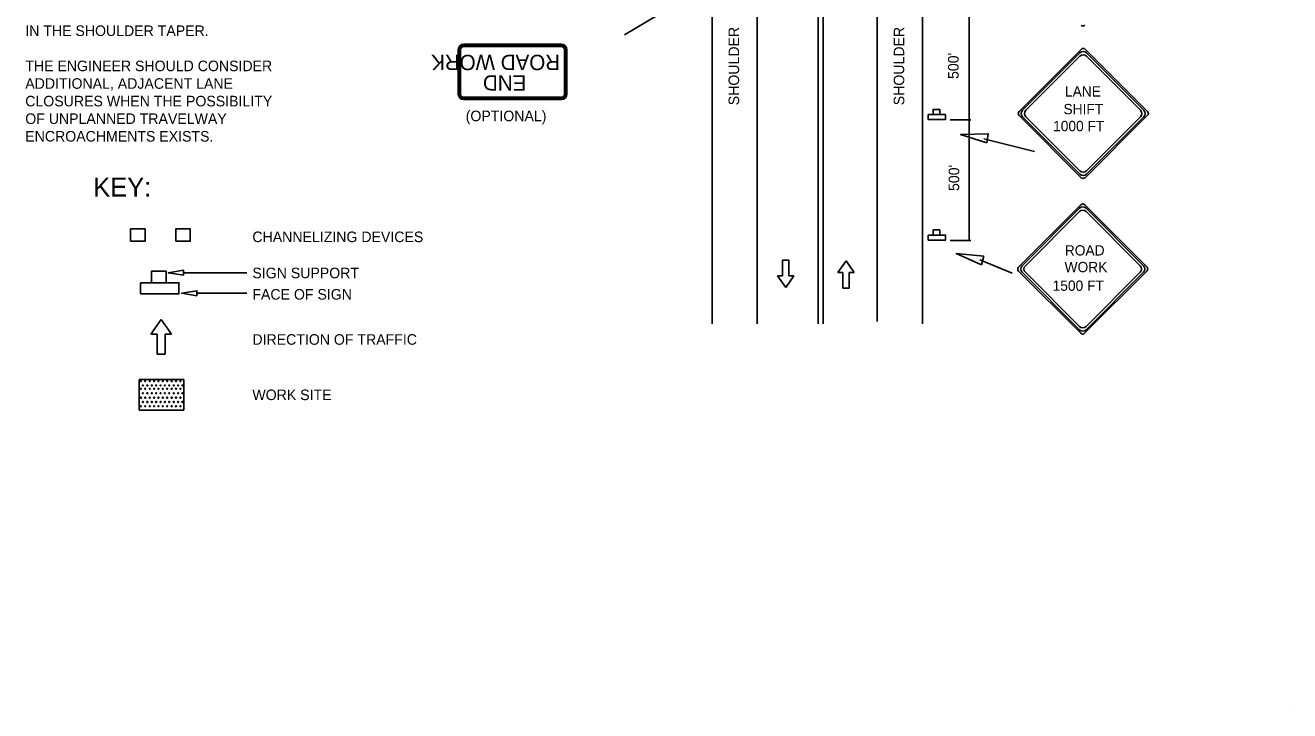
# Model space of a CAD drawing. Extents: x 1531.38 to 1538.58, y 1529.59 to 1539.28.
# Drawn here: x 1531.39 to 1538.58, y 1529.59 to 1533.49 of the extents above; entities that cross this region are included whole.
import ezdxf

# ---------------------------------------------------------------- set-up
doc = ezdxf.new("R2010")
doc.units = 0
for name, color, linetype in [('DETL-DIMS', 7, 'Continuous'), ('DETL-LINE', 7, 'Continuous'), ('DETL-NOTE', 7, 'Continuous'), ('DETL-TITL', 7, 'Continuous'), ('TTLB-TEXT', 7, 'Continuous'), ('USER-BORD', 7, 'Continuous')]:
    doc.layers.add(name, color=color, linetype=linetype)

# ---------------------------------------------------------------- blocks, each defined once
blk = doc.blocks.new('SIGN13')
at = {"layer": 'USER-BORD'}
for points in [[(-0.0134, 0.0182), (0.011, 0.0189), (0.011, 0.0371), (-0.0134, 0.0371)], [(-0.0314, 0.0182), (-0.0314, 0), (0.032, 0), (0.032, 0.0182)]]:
    blk.add_lwpolyline(points, close=True, dxfattribs=at)
blk = doc.blocks.new('DIR2')
at = {"layer": 'USER-BORD'}
for p, q in [((0, 0.0012), (-0.0342, -0.0477)), ((0, 0.0012), (0.0342, -0.0477)), ((-0.0342, -0.0477), (-0.0132, -0.0477)), ((-0.0132, -0.1133), (-0.0132, -0.0477)), ((0.0342, -0.0477), (0.0132, -0.0477)), ((0.0132, -0.1133), (0.0132, -0.0477)), ((-0.0011, -0.1133), (-0.0132, -0.1133)), ((-0.0011, -0.1133), (0.0011, -0.1133)), ((0.0011, -0.1133), (0.0132, -0.1133))]:
    blk.add_line(p, q, dxfattribs=at)
blk = doc.blocks.new('TD')
at = {"layer": 'USER-BORD'}
for p, q in [((0, 0), (-0.0539, -0.077)), ((0, 0), (0.0539, -0.077)), ((-0.0539, -0.077), (-0.0208, -0.077)), ((-0.0208, -0.1803), (-0.0208, -0.077)), ((0.0208, -0.1803), (0.0208, -0.077)), ((0.0539, -0.077), (0.0208, -0.077)), ((-0.0017, -0.1803), (-0.0208, -0.1803)), ((-0.0017, -0.1803), (0.0017, -0.1803)), ((0.0017, -0.1803), (0.0208, -0.1803))]:
    blk.add_line(p, q, dxfattribs=at)

msp = doc.modelspace()

# ---------------------------------------------------------------- linework, layer by layer
at = {"layer": 'DETL-DIMS'}
for p, q in [((1536.7613, 1535.4484), (1536.7613, 1533.1366)), ((1536.7613, 1534.4003), (1536.7613, 1532.2659)), ((1534.9925, 1533.5485), (1534.8025, 1533.4337)), ((1536.6537, 1532.9513), (1536.7703, 1532.9513)), ((1536.8443, 1532.8441), (1537.1327, 1532.7711)), ((1536.6537, 1532.2659), (1536.7703, 1532.2659)), ((1536.823, 1532.1553), (1537.0061, 1532.0801)), ((1532.2934, 1532.0824), (1532.6543, 1532.0824)), ((1532.3705, 1531.9657), (1532.6543, 1531.9657))]:
    msp.add_line(p, q, dxfattribs=at)
for points in [[(1536.8627, 1532.8207), (1536.8701, 1532.8719), (1536.7129, 1532.8682)], [(1536.8313, 1532.1263), (1536.8447, 1532.1763), (1536.6882, 1532.1911)], [(1532.2934, 1532.068), (1532.2934, 1532.0967), (1532.2073, 1532.0824)], [(1532.3705, 1531.9513), (1532.3705, 1531.98), (1532.2844, 1531.9657)]]:
    msp.add_lwpolyline(points, close=True, dxfattribs=at)
at = {"layer": 'DETL-LINE'}
for p, q in [((1535.3002, 1538.9346), (1535.3002, 1531.7918)), ((1535.5552, 1538.9346), (1535.5552, 1531.7918)), ((1535.9039, 1538.9346), (1535.9039, 1531.7918)), ((1535.9309, 1538.9346), (1535.9309, 1531.7918)), ((1536.4962, 1538.9346), (1536.4962, 1531.7918)), ((1536.2393, 1535.6775), (1536.2393, 1531.8053)), ((1533.8562, 1533.3497), (1533.8562, 1533.0974)), ((1533.8626, 1533.0974), (1533.8626, 1533.3497)), ((1533.8699, 1533.0974), (1533.8699, 1533.3497)), ((1534.4426, 1533.3813), (1533.8879, 1533.3813)), ((1533.8879, 1533.3749), (1534.4426, 1533.3749)), ((1533.8879, 1533.3677), (1534.4426, 1533.3677)), ((1534.4609, 1533.3497), (1534.4609, 1533.0974)), ((1534.4676, 1533.3497), (1534.4676, 1533.0974)), ((1534.474, 1533.0974), (1534.474, 1533.3497)), ((1537.4002, 1533.3529), (1537.0455, 1532.9982)), ((1537.7761, 1532.9989), (1537.4221, 1533.3529)), ((1537.0654, 1533.0065), (1537.3915, 1533.3327)), ((1537.3915, 1533.3139), (1537.0843, 1533.0065)), ((1537.7366, 1533.0065), (1537.4292, 1533.3139)), ((1537.4293, 1533.3327), (1537.7554, 1533.0065)), ((1533.8698, 1533.0976), (1533.8699, 1533.0974)), ((1534.4426, 1533.0792), (1533.8879, 1533.0792)), ((1534.4426, 1533.0725), (1533.8879, 1533.0725)), ((1533.8879, 1533.0661), (1534.4426, 1533.0661)), ((1537.7366, 1533.0065), (1537.7366, 1533.0065)), ((1537.0455, 1532.9762), (1537.3994, 1532.6223)), ((1537.3915, 1532.6427), (1537.0654, 1532.9688)), ((1537.0843, 1532.9689), (1537.3915, 1532.6615)), ((1537.4214, 1532.6223), (1537.7761, 1532.977)), ((1537.7554, 1532.9688), (1537.4293, 1532.6427)), ((1537.4293, 1532.6615), (1537.7366, 1532.9688)), ((1537.3971, 1532.4685), (1537.0423, 1532.1138)), ((1537.0623, 1532.1221), (1537.3884, 1532.4483)), ((1537.3884, 1532.4295), (1537.0811, 1532.1221)), ((1537.7729, 1532.1146), (1537.419, 1532.4685)), ((1537.4261, 1532.4483), (1537.7523, 1532.1221)), ((1537.7335, 1532.1221), (1537.4261, 1532.4295)), ((1537.0423, 1532.0919), (1537.3963, 1531.7379)), ((1537.3884, 1531.7583), (1537.0623, 1532.0845)), ((1537.0811, 1532.0845), (1537.3884, 1531.7771)), ((1537.4183, 1531.7379), (1537.7729, 1532.0926)), ((1537.7523, 1532.0845), (1537.4261, 1531.7583)), ((1537.4261, 1531.7771), (1537.7335, 1532.0845)), ((1537.7335, 1532.1221), (1537.7335, 1532.1221)), ((1532.0421, 1531.3011), (1532.0421, 1531.4751)), ((1532.0421, 1531.3011), (1532.0421, 1531.4751)), ((1532.2961, 1531.475), (1532.0421, 1531.475)), ((1532.2961, 1531.475), (1532.0421, 1531.475)), ((1532.2961, 1531.475), (1532.0421, 1531.475)), ((1532.2961, 1531.475), (1532.0421, 1531.475)), ((1532.0507, 1531.4661), (1532.0507, 1531.4661)), ((1532.0507, 1531.4223), (1532.0507, 1531.4223)), ((1532.0515, 1531.4661), (1532.0515, 1531.4661)), ((1532.0515, 1531.4223), (1532.0515, 1531.4223)), ((1532.0635, 1531.4413), (1532.0635, 1531.4413)), ((1532.0635, 1531.4413), (1532.0635, 1531.4413)), ((1532.0763, 1531.4661), (1532.0763, 1531.4661)), ((1532.0763, 1531.4661), (1532.0763, 1531.4661)), ((1532.0763, 1531.4223), (1532.0763, 1531.4223)), ((1532.0763, 1531.4223), (1532.0763, 1531.4223)), ((1532.0883, 1531.4413), (1532.0883, 1531.4413)), ((1532.0883, 1531.4413), (1532.0883, 1531.4413)), ((1532.1011, 1531.4661), (1532.1011, 1531.4661)), ((1532.1011, 1531.4223), (1532.1011, 1531.4223)), ((1532.1019, 1531.4661), (1532.1019, 1531.4661)), ((1532.1019, 1531.4223), (1532.1019, 1531.4223)), ((1532.1139, 1531.4413), (1532.1139, 1531.4413)), ((1532.1139, 1531.4413), (1532.1139, 1531.4413)), ((1532.1259, 1531.4661), (1532.1259, 1531.4661)), ((1532.1259, 1531.4223), (1532.1259, 1531.4223)), ((1532.1267, 1531.4661), (1532.1267, 1531.4661)), ((1532.1267, 1531.4223), (1532.1267, 1531.4223)), ((1532.1387, 1531.4413), (1532.1387, 1531.4413)), ((1532.1387, 1531.4413), (1532.1387, 1531.4413)), ((1532.1507, 1531.4661), (1532.1507, 1531.4661)), ((1532.1507, 1531.4223), (1532.1507, 1531.4223)), ((1532.1515, 1531.4661), (1532.1515, 1531.4661)), ((1532.1515, 1531.4223), (1532.1515, 1531.4223)), ((1532.1635, 1531.4413), (1532.1635, 1531.4413)), ((1532.1635, 1531.4413), (1532.1635, 1531.4413)), ((1532.1763, 1531.4661), (1532.1763, 1531.4661)), ((1532.1763, 1531.4661), (1532.1763, 1531.4661)), ((1532.1763, 1531.4223), (1532.1763, 1531.4223)), ((1532.1763, 1531.4223), (1532.1763, 1531.4223)), ((1532.1883, 1531.4413), (1532.1883, 1531.4413)), ((1532.1883, 1531.4413), (1532.1883, 1531.4413)), ((1532.2011, 1531.4661), (1532.2011, 1531.4661)), ((1532.2011, 1531.4661), (1532.2011, 1531.4661)), ((1532.2011, 1531.4223), (1532.2011, 1531.4223)), ((1532.2011, 1531.4223), (1532.2011, 1531.4223)), ((1532.2131, 1531.4413), (1532.2131, 1531.4413)), ((1532.2131, 1531.4413), (1532.2131, 1531.4413)), ((1532.2259, 1531.4661), (1532.2259, 1531.4661)), ((1532.2259, 1531.4223), (1532.2259, 1531.4223)), ((1532.2267, 1531.4661), (1532.2267, 1531.4661)), ((1532.2267, 1531.4223), (1532.2267, 1531.4223)), ((1532.2387, 1531.4413), (1532.2387, 1531.4413)), ((1532.2387, 1531.4413), (1532.2387, 1531.4413)), ((1532.2507, 1531.4661), (1532.2507, 1531.4661)), ((1532.2507, 1531.4223), (1532.2507, 1531.4223)), ((1532.2515, 1531.4661), (1532.2515, 1531.4661)), ((1532.2515, 1531.4223), (1532.2515, 1531.4223)), ((1532.2635, 1531.4413), (1532.2635, 1531.4413)), ((1532.2635, 1531.4413), (1532.2635, 1531.4413)), ((1532.2763, 1531.4661), (1532.2763, 1531.4661)), ((1532.2763, 1531.4661), (1532.2763, 1531.4661)), ((1532.2763, 1531.4223), (1532.2763, 1531.4223)), ((1532.2763, 1531.4223), (1532.2763, 1531.4223)), ((1532.2883, 1531.4413), (1532.2883, 1531.4413)), ((1532.2883, 1531.4413), (1532.2883, 1531.4413)), ((1532.2961, 1531.301), (1532.2961, 1531.475)), ((1532.2961, 1531.301), (1532.2961, 1531.475)), ((1532.2961, 1531.301), (1532.2961, 1531.475)), ((1532.2961, 1531.301), (1532.2961, 1531.475)), ((1532.0507, 1531.3719), (1532.0507, 1531.3719)), ((1532.0515, 1531.3719), (1532.0515, 1531.3719)), ((1532.0635, 1531.3967), (1532.0635, 1531.3967)), ((1532.0635, 1531.3471), (1532.0635, 1531.3471)), ((1532.0635, 1531.3471), (1532.0635, 1531.3471)), ((1532.0763, 1531.3719), (1532.0763, 1531.3719)), ((1532.0763, 1531.3719), (1532.0763, 1531.3719)), ((1532.0883, 1531.3967), (1532.0883, 1531.3967)), ((1532.0883, 1531.3471), (1532.0883, 1531.3471)), ((1532.0883, 1531.3471), (1532.0883, 1531.3471)), ((1532.1011, 1531.3719), (1532.1011, 1531.3719)), ((1532.1019, 1531.3719), (1532.1019, 1531.3719)), ((1532.1139, 1531.3967), (1532.1139, 1531.3967)), ((1532.1139, 1531.3471), (1532.1139, 1531.3471)), ((1532.1139, 1531.3471), (1532.1139, 1531.3471)), ((1532.1259, 1531.3719), (1532.1259, 1531.3719)), ((1532.1267, 1531.3719), (1532.1267, 1531.3719)), ((1532.1387, 1531.3967), (1532.1387, 1531.3967)), ((1532.1387, 1531.3471), (1532.1387, 1531.3471)), ((1532.1387, 1531.3471), (1532.1387, 1531.3471)), ((1532.1507, 1531.3719), (1532.1507, 1531.3719)), ((1532.1515, 1531.3719), (1532.1515, 1531.3719)), ((1532.1635, 1531.3967), (1532.1635, 1531.3967)), ((1532.1635, 1531.3471), (1532.1635, 1531.3471)), ((1532.1635, 1531.3471), (1532.1635, 1531.3471)), ((1532.1763, 1531.3719), (1532.1763, 1531.3719)), ((1532.1763, 1531.3719), (1532.1763, 1531.3719)), ((1532.1883, 1531.3967), (1532.1883, 1531.3967)), ((1532.1883, 1531.3471), (1532.1883, 1531.3471)), ((1532.1883, 1531.3471), (1532.1883, 1531.3471)), ((1532.2011, 1531.3719), (1532.2011, 1531.3719)), ((1532.2011, 1531.3719), (1532.2011, 1531.3719)), ((1532.2131, 1531.3967), (1532.2131, 1531.3967)), ((1532.2131, 1531.3471), (1532.2131, 1531.3471)), ((1532.2131, 1531.3471), (1532.2131, 1531.3471)), ((1532.2259, 1531.3719), (1532.2259, 1531.3719)), ((1532.2267, 1531.3719), (1532.2267, 1531.3719)), ((1532.2387, 1531.3967), (1532.2387, 1531.3967)), ((1532.2387, 1531.3471), (1532.2387, 1531.3471)), ((1532.2387, 1531.3471), (1532.2387, 1531.3471)), ((1532.2507, 1531.3719), (1532.2507, 1531.3719)), ((1532.2515, 1531.3719), (1532.2515, 1531.3719)), ((1532.2635, 1531.3967), (1532.2635, 1531.3967)), ((1532.2635, 1531.3471), (1532.2635, 1531.3471)), ((1532.2635, 1531.3471), (1532.2635, 1531.3471)), ((1532.2763, 1531.3719), (1532.2763, 1531.3719)), ((1532.2763, 1531.3719), (1532.2763, 1531.3719)), ((1532.2883, 1531.3967), (1532.2883, 1531.3967)), ((1532.2883, 1531.3471), (1532.2883, 1531.3471)), ((1532.2883, 1531.3471), (1532.2883, 1531.3471)), ((1532.0421, 1531.3011), (1532.2961, 1531.3011)), ((1532.0507, 1531.3227), (1532.0507, 1531.3227)), ((1532.0515, 1531.3227), (1532.0515, 1531.3227)), ((1532.0763, 1531.3227), (1532.0763, 1531.3227)), ((1532.0763, 1531.3227), (1532.0763, 1531.3227)), ((1532.1011, 1531.3227), (1532.1011, 1531.3227)), ((1532.1019, 1531.3227), (1532.1019, 1531.3227)), ((1532.1259, 1531.3227), (1532.1259, 1531.3227)), ((1532.1267, 1531.3227), (1532.1267, 1531.3227)), ((1532.1507, 1531.3227), (1532.1507, 1531.3227)), ((1532.1515, 1531.3227), (1532.1515, 1531.3227)), ((1532.1763, 1531.3227), (1532.1763, 1531.3227)), ((1532.1763, 1531.3227), (1532.1763, 1531.3227)), ((1532.2011, 1531.3227), (1532.2011, 1531.3227)), ((1532.2011, 1531.3227), (1532.2011, 1531.3227)), ((1532.2259, 1531.3227), (1532.2259, 1531.3227)), ((1532.2267, 1531.3227), (1532.2267, 1531.3227)), ((1532.2507, 1531.3227), (1532.2507, 1531.3227)), ((1532.2515, 1531.3227), (1532.2515, 1531.3227)), ((1532.2763, 1531.3227), (1532.2763, 1531.3227)), ((1532.2763, 1531.3227), (1532.2763, 1531.3227))]:
    msp.add_line(p, q, dxfattribs=at)
for points in [[(1531.9928, 1532.2613), (1531.9928, 1532.3309), (1532.0754, 1532.3309), (1532.0754, 1532.2613)], [(1532.2498, 1532.2613), (1532.2498, 1532.3309), (1532.3324, 1532.3309), (1532.3324, 1532.2613)]]:
    msp.add_lwpolyline(points, close=True, dxfattribs=at)
for centre in [(1532.0514, 1531.4661), (1532.0514, 1531.4224), (1532.0634, 1531.4413), (1532.0762, 1531.4661), (1532.0762, 1531.4224), (1532.0882, 1531.4413), (1532.1018, 1531.4661), (1532.1018, 1531.4224), (1532.1138, 1531.4413), (1532.1266, 1531.4661), (1532.1266, 1531.4224), (1532.1386, 1531.4413), (1532.1514, 1531.4661), (1532.1514, 1531.4224), (1532.1634, 1531.4413), (1532.1762, 1531.4661), (1532.1762, 1531.4224), (1532.1882, 1531.4413), (1532.201, 1531.4661), (1532.201, 1531.4224), (1532.213, 1531.4413), (1532.2266, 1531.4661), (1532.2266, 1531.4224), (1532.2386, 1531.4413), (1532.2514, 1531.4661), (1532.2514, 1531.4224), (1532.2634, 1531.4413), (1532.2762, 1531.4661), (1532.2762, 1531.4224), (1532.2882, 1531.4413), (1532.0514, 1531.372), (1532.0634, 1531.3968), (1532.0634, 1531.3472), (1532.0762, 1531.372), (1532.0882, 1531.3968), (1532.0882, 1531.3472), (1532.1018, 1531.372), (1532.1138, 1531.3968), (1532.1138, 1531.3472), (1532.1266, 1531.372), (1532.1386, 1531.3968), (1532.1386, 1531.3472), (1532.1514, 1531.372), (1532.1634, 1531.3968), (1532.1634, 1531.3472), (1532.1762, 1531.372), (1532.1882, 1531.3968), (1532.1882, 1531.3472), (1532.201, 1531.372), (1532.213, 1531.3968), (1532.213, 1531.3472), (1532.2266, 1531.372), (1532.2386, 1531.3968), (1532.2386, 1531.3472), (1532.2514, 1531.372), (1532.2634, 1531.3968), (1532.2634, 1531.3472), (1532.2762, 1531.372), (1532.2882, 1531.3968), (1532.2882, 1531.3472), (1532.0514, 1531.3228), (1532.0762, 1531.3228), (1532.1018, 1531.3228), (1532.1266, 1531.3228), (1532.1514, 1531.3228), (1532.1762, 1531.3228), (1532.201, 1531.3228), (1532.2266, 1531.3228), (1532.2514, 1531.3228), (1532.2762, 1531.3228)]:
    msp.add_circle(centre, 0.00291, dxfattribs=at)
for centre, radius, start, end in [((1537.4086, 1533.4996), 0.0155, 225, 315), ((1533.8879, 1533.3497), 0.0316, 90, 180), ((1533.8879, 1533.3497), 0.0252, 90, 180), ((1533.8879, 1533.3497), 0.0181, 90, 180), ((1534.4425, 1533.3497), 0.0316, 0, 90), ((1534.4425, 1533.3497), 0.0252, 0, 90), ((1534.4425, 1533.3497), 0.0181, 0, 90), ((1537.4112, 1533.3419), 0.0155, 45, 135), ((1537.4104, 1533.3138), 0.0266, 45, 135), ((1537.4104, 1533.295), 0.0266, 45, 135), ((1533.8879, 1533.0976), 0.0316, 180, 270), ((1533.8879, 1533.0976), 0.0252, 180, 270), ((1533.8879, 1533.0976), 0.0181, 180, 270), ((1534.4425, 1533.0976), 0.0316, 270, 0), ((1534.4425, 1533.0976), 0.0252, 270, 0), ((1534.4425, 1533.0976), 0.0181, 270, 0), ((1537.0565, 1532.9872), 0.0155, 135, 225), ((1537.0842, 1532.9876), 0.0266, 135, 225), ((1537.103, 1532.9877), 0.0266, 135, 225), ((1537.7178, 1532.9876), 0.0266, 315, 45), ((1537.7366, 1532.9876), 0.0266, 315, 45), ((1537.7651, 1532.988), 0.0155, 315, 45), ((1537.4104, 1532.6803), 0.0266, 225, 315), ((1537.4104, 1532.6614), 0.0266, 225, 315), ((1537.4104, 1532.6332), 0.0155, 225, 315), ((1537.4073, 1532.4107), 0.0266, 45, 135), ((1537.4073, 1532.4295), 0.0266, 45, 135), ((1537.4081, 1532.4575), 0.0155, 45, 135), ((1537.0533, 1532.1028), 0.0155, 135, 225), ((1537.0811, 1532.1033), 0.0266, 135, 225), ((1537.0999, 1532.1033), 0.0266, 135, 225), ((1537.7146, 1532.1033), 0.0266, 315, 45), ((1537.7335, 1532.1033), 0.0266, 315, 45), ((1537.762, 1532.1036), 0.0155, 315, 45), ((1537.4073, 1531.7959), 0.0266, 225, 315), ((1537.4073, 1531.7771), 0.0266, 225, 315), ((1537.4073, 1531.7489), 0.0155, 225, 315)]:
    msp.add_arc(centre, radius, start, end, dxfattribs=at)
at = {"layer": 'TTLB-TEXT'}
msp.add_line((1538.5844, 1529.5924), (1538.5844, 1529.5924), dxfattribs=at)

# ---------------------------------------------------------------- block references
at = {"layer": 'DETL-LINE'}
for name, p, xscale, yscale in [('SIGN13', (1536.5771, 1532.9533), 1.550372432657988, 1.550372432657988), ('SIGN13', (1536.5777, 1532.2679), 1.550372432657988, 1.550372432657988), ('TD', (1536.0618, 1532.1502), 0.8611764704, 0.8611764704), ('SIGN13', (1532.158, 1531.9623), 3.4447058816, 3.4447058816), ('DIR2', (1532.1672, 1531.8148), 1.7223529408, 1.7223529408)]:
    msp.add_blockref(name, p, dxfattribs=dict(at, xscale=xscale, yscale=yscale))
at = {"layer": 'DETL-LINE', "xscale": 0.8611764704, "yscale": 0.8611764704, "rotation": 180}
msp.add_blockref('TD', (1535.719, 1531.9991), dxfattribs=at)

# ---------------------------------------------------------------- texts
at = {"layer": 'DETL-LINE'}
for s, p in [('ROAD WORK', (1534.4353, 1533.3211)), ('END', (1534.2433, 1533.2051))]:
    msp.add_text(s, height=0.08731, rotation=180, dxfattribs=at).set_placement(p)
for s, p in [('LANE', (1537.3064, 1533.0835)), ('SHIFT', (1537.2979, 1532.9831)), ('1000 FT', (1537.2388, 1532.8867)), ('ROAD', (1537.3055, 1532.18)), ('WORK', (1537.3041, 1532.085)), ('1500 FT', (1537.2363, 1531.9793))]:
    msp.add_text(s, height=0.05854, dxfattribs=at).set_placement(p)
at = {"layer": 'DETL-NOTE'}
for s, p in [('IN THE SHOULDER TAPER.', (1531.3942, 1533.4278)), ('THE ENGINEER SHOULD CONSIDER', (1531.3942, 1533.2278)), ('ADDITIONAL, ADJACENT LANE', (1531.3942, 1533.1278)), ('CLOSURES WHEN THE POSSIBILITY', (1531.3942, 1533.0278)), ('(OPTIONAL)', (1533.8987, 1532.9435)), ('OF UNPLANNED TRAVELWAY', (1531.3942, 1532.9278)), ('ENCROACHMENTS EXISTS.', (1531.3942, 1532.8278)), ('CHANNELIZING DEVICES', (1532.6857, 1532.2561)), ('SIGN SUPPORT', (1532.6857, 1532.0508)), ('FACE OF SIGN', (1532.6857, 1531.9293)), ('DIRECTION OF TRAFFIC', (1532.6857, 1531.6727)), ('WORK SITE', (1532.6857, 1531.3581))]:
    msp.add_text(s, height=0.06, dxfattribs=at).set_placement(p)
for s, p in [('SHOULDER', (1535.4535, 1533.0341)), ('SHOULDER', (1536.3925, 1533.0341)), ("500'", (1536.7015, 1533.1834)), ("500'", (1536.705, 1532.5466))]:
    msp.add_text(s, height=0.06, rotation=90, dxfattribs=at).set_placement(p)
at = {"layer": 'DETL-TITL'}
msp.add_text('KEY:', height=0.108, dxfattribs=at).set_placement((1531.7813, 1532.5149))

doc.saveas('drawing.dxf')
